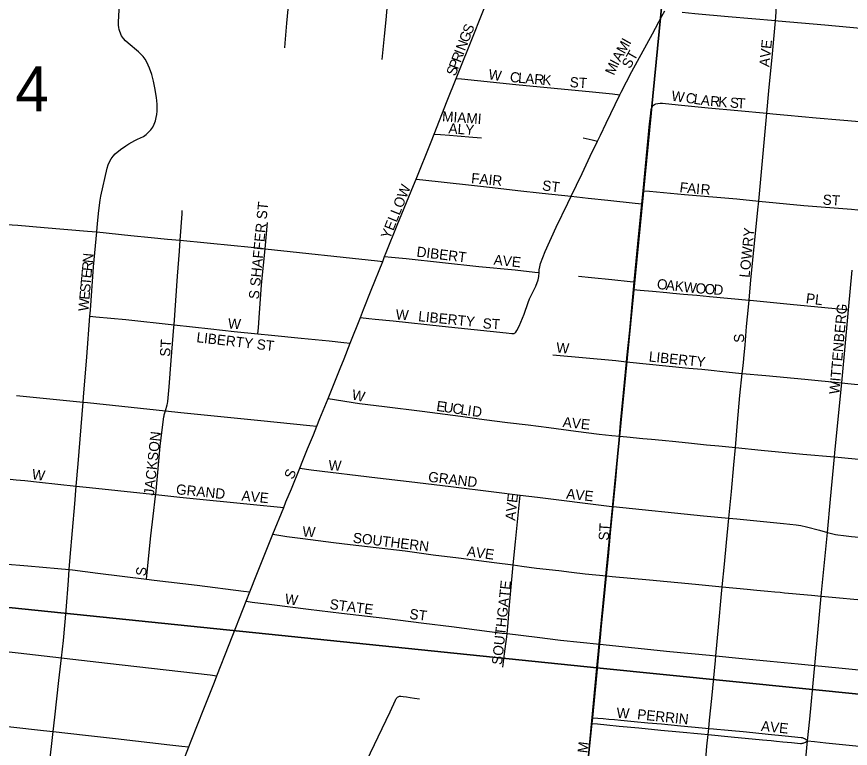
# Model space of a CAD drawing. Extents: x -209 to 4852, y 0 to 905.
# Drawn here: x 96.2 to 111.69, y 254.19 to 267.79 of the extents above; entities that cross this region are included whole.
import ezdxf

# ---------------------------------------------------------------- set-up
doc = ezdxf.new("R2010")
doc.units = 0
for name, color, linetype in [('GM_X_Airport_Location_Class_2', 7, 'Continuous'), ('GM_X_Airport_Location_Class_3', 7, 'Continuous'), ('GM_X_Minor_River', 7, 'Continuous'), ('GM_X_Township_Road_Text', 7, 'Continuous')]:
    doc.layers.add(name, color=color, linetype=linetype)

msp = doc.modelspace()

# ---------------------------------------------------------------- linework, layer by layer
at = {"layer": 'GM_X_Airport_Location_Class_2'}
for points in [[(98.148, 267.436), (98.115, 267.514), (98.106, 267.55), (98.1, 267.588), (98.095, 267.632), (98.095, 267.687), (98.11, 268.03), (98.113, 268.107), (98.116, 268.192), (98.12, 268.319), (98.123, 268.4), (98.126, 268.483), (98.137, 268.607), (98.165, 268.915)], [(101.183, 267.213), (101.192, 267.298), (101.222, 267.669), (101.31, 268.581)], [(110.301, 267.713), (110.307, 267.791), (110.32, 267.982), (110.359, 268.413), (110.36, 268.419)], [(102.994, 266.997), (103.037, 267.427), (103.063, 267.735), (103.102, 268.168), (103.12, 268.388)], [(104.366, 266.644), (104.706, 267.489), (104.801, 267.725), (104.986, 268.2)], [(107.408, 266.341), (107.43, 266.387), (107.627, 266.771), (108.015, 267.474), (108.188, 267.799), (108.242, 267.9)], [(110.301, 267.713), (109.421, 267.791), (108.799, 267.847), (108.564, 267.87)], [(110.137, 265.996), (110.175, 266.413), (110.241, 267.099), (110.301, 267.713)], [(112.145, 267.546), (111.215, 267.631), (110.349, 267.709), (110.301, 267.713)], [(97.767, 264.452), (97.883, 264.977), (97.902, 265.037), (97.924, 265.095), (97.954, 265.149), (97.991, 265.199), (98.034, 265.244), (98.13, 265.324), (98.229, 265.392), (98.282, 265.425), (98.34, 265.46), (98.394, 265.488), (98.449, 265.513), (98.504, 265.538), (98.559, 265.566), (98.605, 265.601), (98.652, 265.642), (98.694, 265.689), (98.729, 265.74), (98.758, 265.795), (98.779, 265.853), (98.795, 265.914), (98.805, 265.975), (98.809, 266.037), (98.809, 266.162), (98.798, 266.286), (98.77, 266.471), (98.744, 266.593), (98.711, 266.714), (98.669, 266.831), (98.618, 266.946), (98.587, 267), (98.552, 267.05), (98.511, 267.097), (98.465, 267.14), (98.27, 267.296), (98.224, 267.339), (98.183, 267.385), (98.148, 267.436)], [(103.955, 265.606), (104.197, 266.225), (104.366, 266.644)], [(104.366, 266.644), (104.468, 266.634), (105.477, 266.531), (106.9, 266.397), (107.272, 266.356), (107.408, 266.341)], [(106.995, 265.478), (107.049, 265.59), (107.156, 265.812), (107.408, 266.341)], [(107.839, 264.555), (107.961, 265.802), (107.982, 265.999), (107.989, 266.069), (107.993, 266.086), (107.999, 266.102), (108.007, 266.117), (108.019, 266.131)], [(108.019, 266.131), (108.034, 266.144), (108.053, 266.157), (108.079, 266.169), (108.113, 266.179), (108.159, 266.182), (108.201, 266.181), (108.491, 266.15), (109.05, 266.099), (109.601, 266.045), (110.137, 265.996)], [(109.988, 264.363), (110.062, 265.18), (110.137, 265.996)], [(110.137, 265.996), (110.252, 265.986), (110.521, 265.961), (111.054, 265.913), (111.497, 265.873), (111.86, 265.84), (111.98, 265.83)], [(103.621, 264.77), (103.899, 265.462), (103.955, 265.606)], [(103.955, 265.606), (104.075, 265.599), (104.243, 265.589), (104.383, 265.576), (104.674, 265.549), (104.835, 265.538)], [(106.504, 264.454), (106.605, 264.656), (106.707, 264.876), (106.859, 265.2), (106.995, 265.478)], [(106.724, 265.538), (106.781, 265.528), (106.893, 265.502), (106.995, 265.478)], [(103.038, 263.332), (103.068, 263.406), (103.273, 263.918), (103.574, 264.652), (103.621, 264.77)], [(103.621, 264.77), (103.748, 264.756), (104.596, 264.663), (105.041, 264.614), (105.51, 264.562), (105.966, 264.513), (106.504, 264.454)], [(107.815, 264.311), (107.828, 264.439), (107.839, 264.555)], [(107.839, 264.555), (107.956, 264.545), (108.608, 264.488), (109.582, 264.402), (109.988, 264.363)], [(97.689, 263.789), (97.704, 263.946), (97.728, 264.191), (97.755, 264.378), (97.767, 264.452)], [(105.907, 263.033), (105.91, 263.083), (105.918, 263.143), (105.934, 263.201), (105.975, 263.315), (106.021, 263.428), (106.226, 263.879), (106.44, 264.324), (106.504, 264.454)], [(106.504, 264.454), (106.821, 264.419), (107.185, 264.38), (107.689, 264.325), (107.815, 264.311)], [(107.674, 262.863), (107.759, 263.76), (107.815, 264.311)], [(109.809, 262.521), (109.844, 262.9), (109.918, 263.637), (109.973, 264.199), (109.988, 264.363)], [(109.988, 264.363), (110.826, 264.284), (111.709, 264.21), (111.826, 264.2)], [(99.241, 263.634), (99.273, 264.125), (99.276, 264.189)], [(96.014, 263.93), (96.224, 263.913), (96.711, 263.873), (97.517, 263.806), (97.689, 263.789)], [(100.817, 263.478), (100.864, 263.968)], [(97.561, 262.221), (97.57, 262.333), (97.631, 263.14), (97.689, 263.789)], [(97.689, 263.789), (98.322, 263.726), (98.699, 263.688), (99.003, 263.658), (99.241, 263.634)], [(99.125, 262.062), (99.158, 262.516), (99.192, 262.967), (99.228, 263.434), (99.241, 263.634)], [(99.241, 263.634), (100.241, 263.535), (100.747, 263.485), (100.817, 263.478)], [(100.683, 261.897), (100.692, 262.01), (100.707, 262.193), (100.751, 262.806), (100.817, 263.478)], [(100.817, 263.478), (102.902, 263.254), (103.003, 263.243)], [(103.003, 263.243), (103.038, 263.332)], [(103.038, 263.332), (103.167, 263.32), (103.437, 263.296), (104.787, 263.15), (105.463, 263.085), (105.831, 263.042), (105.907, 263.033)], [(102.586, 262.2), (102.645, 262.35), (102.789, 262.71), (103.003, 263.243)], [(105.464, 261.913), (105.478, 261.929), (105.495, 261.959), (105.536, 262.037), (105.632, 262.261), (105.705, 262.479), (105.73, 262.543), (105.762, 262.61), (105.848, 262.779), (105.891, 262.897), (105.903, 262.959), (105.907, 263.033)], [(111.655, 262.343), (111.724, 263.079)], [(106.642, 262.968), (106.883, 262.943), (107.256, 262.906), (107.601, 262.871), (107.674, 262.863)], [(107.662, 262.722), (107.674, 262.863)], [(107.531, 261.377), (107.537, 261.447), (107.59, 261.966), (107.648, 262.583), (107.662, 262.722)], [(107.662, 262.722), (107.785, 262.71), (108.013, 262.689), (108.283, 262.664), (108.389, 262.654), (108.593, 262.635), (108.837, 262.612), (109.075, 262.589), (109.809, 262.521)], [(109.683, 261.16), (109.692, 261.248), (109.702, 261.36), (109.716, 261.504), (109.733, 261.685), (109.763, 262.03), (109.797, 262.39), (109.809, 262.521)], [(109.809, 262.521), (109.826, 262.519), (110.569, 262.444), (111.54, 262.354), (111.655, 262.343)], [(97.438, 260.627), (97.445, 260.72), (97.502, 261.465), (97.561, 262.221)], [(97.561, 262.221), (97.672, 262.211), (98.227, 262.159), (99.125, 262.062)], [(111.529, 260.984), (111.599, 261.731), (111.655, 262.343)], [(98.965, 260.465), (98.997, 260.574), (99.003, 260.603), (99.008, 260.638), (99.035, 260.908), (99.073, 261.402), (99.097, 261.712), (99.123, 262.021), (99.125, 262.062)], [(99.125, 262.062), (99.807, 261.989), (100.245, 261.941), (100.683, 261.897)], [(102.4, 261.725), (102.586, 262.2)], [(102.586, 262.2), (102.742, 262.183), (102.86, 262.171), (103.197, 262.135), (104.105, 262.038), (105.295, 261.911), (105.403, 261.901), (105.422, 261.901), (105.438, 261.901), (105.447, 261.903), (105.453, 261.905), (105.464, 261.913)], [(100.683, 261.897), (100.937, 261.872), (101.485, 261.817), (102.008, 261.764), (102.281, 261.737), (102.4, 261.725)], [(101.991, 260.691), (102.214, 261.249), (102.285, 261.432), (102.4, 261.725)], [(106.165, 261.503), (107.332, 261.397), (107.531, 261.377)], [(107.4, 259.993), (107.42, 260.233), (107.475, 260.8), (107.531, 261.377)], [(107.531, 261.377), (108.686, 261.26), (108.933, 261.236), (109.102, 261.219), (109.32, 261.197), (109.621, 261.166), (109.683, 261.16)], [(109.553, 259.782), (109.56, 259.859), (109.594, 260.249), (109.637, 260.747), (109.683, 261.16)], [(109.683, 261.16), (110.118, 261.119), (110.842, 261.05), (111.529, 260.984)], [(111.394, 259.608), (111.401, 259.686), (111.478, 260.431), (111.529, 260.984)], [(111.529, 260.984), (111.645, 260.973), (112.588, 260.881)], [(96.2, 260.751), (97.438, 260.627)], [(101.778, 260.176), (101.835, 260.32), (101.991, 260.691)], [(101.991, 260.691), (102.568, 260.602), (103.032, 260.544), (103.732, 260.457), (104.447, 260.363), (104.791, 260.318), (105.081, 260.28), (105.322, 260.25), (105.703, 260.201), (106.091, 260.152), (106.59, 260.087), (107.024, 260.032), (107.258, 260.005), (107.4, 259.993)], [(97.309, 259.064), (97.345, 259.479), (97.438, 260.627)], [(97.438, 260.627), (97.52, 260.618), (98.965, 260.465)], [(98.784, 258.909), (98.819, 259.249), (98.865, 259.808), (98.904, 260.11), (98.936, 260.353), (98.94, 260.371), (98.944, 260.391), (98.965, 260.465)], [(98.965, 260.465), (99.25, 260.435), (100.24, 260.337), (100.74, 260.284), (101.648, 260.19), (101.778, 260.176)], [(101.459, 259.396), (101.519, 259.538), (101.607, 259.76), (101.715, 260.019), (101.778, 260.176)], [(107.285, 258.685), (107.333, 259.179), (107.364, 259.551), (107.4, 259.993)], [(107.4, 259.993), (107.54, 259.98), (107.835, 259.951), (107.995, 259.935), (108.191, 259.916), (108.447, 259.891), (108.737, 259.862), (109.017, 259.834), (109.248, 259.812), (109.432, 259.793), (109.553, 259.782)], [(109.433, 258.468), (109.479, 258.964), (109.525, 259.458), (109.553, 259.782)], [(109.553, 259.782), (110.031, 259.734), (110.805, 259.658), (111.394, 259.608)], [(111.263, 258.205), (111.321, 258.823), (111.394, 259.608)], [(111.394, 259.608), (111.527, 259.597), (111.844, 259.567), (112.075, 259.545), (112.373, 259.516), (112.687, 259.486), (113.077, 259.449), (113.461, 259.413), (113.579, 259.404)], [(101.162, 258.667), (101.204, 258.771), (101.305, 259.012), (101.459, 259.396)], [(101.459, 259.396), (101.674, 259.369), (102.905, 259.219), (103.493, 259.149), (104.265, 259.057), (105.068, 258.959), (105.554, 258.899)], [(96.081, 259.194), (96.19, 259.183), (96.35, 259.166), (96.624, 259.137), (97.309, 259.064)], [(97.177, 257.512), (97.192, 257.743), (97.28, 258.735), (97.309, 259.064)], [(97.309, 259.064), (97.555, 259.038), (98.61, 258.928), (98.784, 258.909)], [(98.613, 257.336), (98.626, 257.457), (98.658, 257.774), (98.695, 258.138), (98.74, 258.508), (98.781, 258.879), (98.784, 258.909)], [(98.784, 258.909), (99.231, 258.862), (100.661, 258.718), (101.039, 258.679), (101.162, 258.667)], [(105.426, 257.599), (105.467, 258.029), (105.542, 258.773), (105.554, 258.899)], [(105.554, 258.899), (105.875, 258.86), (107.212, 258.693), (107.285, 258.685)], [(100.963, 258.174), (101.162, 258.667)], [(107.16, 257.396), (107.194, 257.755), (107.236, 258.188), (107.285, 258.685)], [(107.285, 258.685), (108.959, 258.513), (109.433, 258.468)], [(109.31, 257.191), (109.35, 257.614), (109.391, 258.019), (109.433, 258.468)], [(109.433, 258.468), (109.58, 258.454), (110.445, 258.372), (110.682, 258.345), (110.772, 258.331), (110.874, 258.309), (111.114, 258.244), (111.263, 258.205)], [(111.149, 257.022), (111.155, 257.089), (111.204, 257.584), (111.263, 258.205)], [(111.263, 258.205), (111.363, 258.179), (111.415, 258.167), (111.455, 258.16), (111.563, 258.146), (111.711, 258.128), (112.043, 258.1), (112.577, 258.05), (113.02, 258.014), (113.445, 257.972)], [(100.534, 257.098), (100.664, 257.426), (100.963, 258.174)], [(100.963, 258.174), (101.222, 258.131), (101.52, 258.091), (102.087, 258.019), (102.399, 257.98), (103.416, 257.859), (103.939, 257.787), (104.411, 257.729), (105.071, 257.647), (105.426, 257.599)], [(95.954, 257.623), (96.41, 257.58), (96.967, 257.534), (97.177, 257.512)], [(105.312, 256.323), (105.325, 256.446), (105.355, 256.852), (105.426, 257.599)], [(105.426, 257.599), (105.586, 257.578), (105.862, 257.54), (106.273, 257.493), (106.507, 257.465), (106.765, 257.434), (107.16, 257.396)], [(97.034, 255.871), (97.069, 256.193), (97.123, 256.75), (97.164, 257.308), (97.177, 257.512)], [(97.177, 257.512), (97.236, 257.506), (97.707, 257.449), (98.613, 257.336)], [(98.613, 257.336), (98.754, 257.319), (99.555, 257.222), (100.417, 257.113), (100.534, 257.098)], [(107.036, 256.127), (107.055, 256.316), (107.069, 256.465), (107.112, 256.889), (107.16, 257.396)], [(107.16, 257.396), (107.265, 257.386), (107.956, 257.32), (108.812, 257.239), (109.31, 257.191)], [(109.191, 255.911), (109.24, 256.443), (109.298, 257.06), (109.31, 257.191)], [(109.31, 257.191), (109.772, 257.147), (109.955, 257.13), (110.157, 257.112), (110.289, 257.1), (110.387, 257.091), (110.467, 257.084), (110.615, 257.07), (110.754, 257.058), (110.971, 257.038), (111.149, 257.022)], [(100.465, 256.925), (100.534, 257.098)], [(111.03, 255.729), (111.095, 256.407), (111.149, 257.022)], [(111.149, 257.022), (111.486, 256.991), (111.756, 256.966), (112.193, 256.926), (112.709, 256.879), (113.176, 256.834), (113.339, 256.818)], [(99.922, 255.54), (100.15, 256.118), (100.465, 256.925)], [(100.465, 256.925), (100.578, 256.91), (100.942, 256.864), (101.626, 256.78), (102.239, 256.705), (103.041, 256.607), (103.766, 256.518), (104.278, 256.455), (105.224, 256.333), (105.312, 256.323)], [(105.236, 255.697), (105.266, 255.944), (105.289, 256.133), (105.305, 256.261), (105.312, 256.323)], [(105.312, 256.323), (105.87, 256.255), (106.307, 256.202), (107.036, 256.127)], [(94.6, 256.146), (94.691, 256.136), (95.182, 256.083), (96.226, 255.963), (97.034, 255.871)], [(106.906, 254.759), (106.968, 255.403), (107.023, 256.003), (107.036, 256.127)], [(107.036, 256.127), (108.339, 255.992), (109.072, 255.922), (109.191, 255.911)], [(96.879, 254.502), (96.908, 254.77), (96.987, 255.45), (97.034, 255.871)], [(97.034, 255.871), (97.086, 255.865), (97.886, 255.772), (99.795, 255.554), (99.922, 255.54)], [(109.058, 254.562), (109.073, 254.715), (109.117, 255.119), (109.183, 255.822), (109.191, 255.911)], [(109.191, 255.911), (109.619, 255.869), (110.201, 255.812), (110.719, 255.761), (111.03, 255.729)], [(110.895, 254.329), (110.936, 254.735), (111.018, 255.602), (111.03, 255.729)], [(111.03, 255.729), (111.478, 255.685), (112.034, 255.629), (113.214, 255.516)], [(99.4, 254.216), (99.444, 254.329), (99.679, 254.924), (99.874, 255.419), (99.922, 255.54)], [(103.24, 255.085), (103.248, 255.102), (103.256, 255.116), (103.266, 255.13), (103.274, 255.14), (103.286, 255.148), (103.299, 255.154), (103.313, 255.157), (103.327, 255.159), (103.34, 255.159), (103.38, 255.154), (103.441, 255.145), (103.512, 255.135), (103.594, 255.124), (103.683, 255.111)], [(102.594, 253.729), (102.626, 253.796), (103.138, 254.867), (103.24, 255.085)], [(94.441, 254.773), (94.823, 254.731), (95.384, 254.669), (96.095, 254.59), (96.702, 254.523), (96.879, 254.502)], [(106.751, 253.268), (106.761, 253.374), (106.787, 253.622), (106.815, 253.892), (106.833, 254.056), (106.89, 254.598), (106.895, 254.653)], [(106.895, 254.653), (106.906, 254.759)], [(106.895, 254.653), (106.991, 254.643), (107.167, 254.626), (107.396, 254.603), (107.76, 254.569), (108.17, 254.53), (108.515, 254.498), (108.916, 254.46), (109.047, 254.448)], [(106.906, 254.759), (106.998, 254.751), (107.097, 254.743), (107.201, 254.734), (107.305, 254.725), (107.423, 254.715), (107.674, 254.691), (107.927, 254.667), (108.181, 254.643), (108.542, 254.608), (108.936, 254.571), (109.058, 254.562)], [(96.728, 253.147), (96.744, 253.286), (96.808, 253.842), (96.879, 254.502)], [(96.879, 254.502), (97.483, 254.434), (98.035, 254.371), (99.044, 254.256), (99.269, 254.23), (99.4, 254.216)], [(109.047, 254.448), (109.058, 254.562)], [(109.058, 254.562), (109.146, 254.555), (109.211, 254.549), (109.351, 254.535), (109.489, 254.522), (109.696, 254.501), (109.877, 254.483), (110.161, 254.455), (110.476, 254.424), (110.778, 254.394), (110.793, 254.391), (110.808, 254.386), (110.821, 254.381), (110.835, 254.375), (110.851, 254.365), (110.866, 254.355), (110.895, 254.329)], [(108.92, 253.057), (108.933, 253.184), (108.959, 253.482), (109.004, 253.992), (109.026, 254.23), (109.047, 254.448)], [(109.047, 254.448), (109.477, 254.406), (110.057, 254.349), (110.22, 254.333), (110.318, 254.324), (110.438, 254.312), (110.517, 254.304), (110.598, 254.296), (110.765, 254.28), (110.782, 254.282), (110.796, 254.284), (110.813, 254.287), (110.826, 254.291), (110.845, 254.298), (110.859, 254.306), (110.895, 254.329)], [(110.754, 252.877), (110.842, 253.806), (110.895, 254.329)], [(110.895, 254.329), (111.024, 254.316), (111.236, 254.295), (112.038, 254.215), (112.54, 254.165)], [(98.884, 252.892), (99.082, 253.4), (99.4, 254.216)]]:
    msp.add_lwpolyline(points, dxfattribs=at)
at = {"layer": 'GM_X_Minor_River'}
for points in [[(88.927, 277.384), (108.909, 275.428), (106.979, 255.688), (87.119, 257.725)], [(108.909, 275.428), (129.104, 273.545), (127.195, 253.652), (106.979, 255.688)], [(87.119, 257.725), (106.979, 255.688), (105.036, 235.054), (84.904, 237.096)], [(106.979, 255.688), (127.195, 253.652), (125.307, 233.161), (105.036, 235.054)]]:
    msp.add_lwpolyline(points, close=True, dxfattribs=at)

# ---------------------------------------------------------------- texts
at = {"layer": 'GM_X_Airport_Location_Class_3'}
for s, height, rotation, p in [('S', 0.189, 66.5646, (104.648, 267.452)), ('G', 0.189, 69.1037, (104.59, 267.298)), ('N', 0.189, 69.122, (104.53, 267.143)), ('M', 0.189, 60.6279, (107.496, 267.086)), ('I', 0.189, 60.6525, (107.594, 267.261)), ('AVE', 0.1894, 84.0895, (110.183, 266.85)), ('I', 0.189, 69.0833, (104.5, 267.065)), ('ST', 0.1894, 60.2568, (107.594, 266.81)), ('R', 0.189, 69.1026, (104.447, 266.925)), ('A', 0.189, 60.6428, (107.414, 266.941)), ('S', 0.189, 69.1066, (104.352, 266.675)), ('P', 0.189, 69.0978, (104.399, 266.8)), ('M', 0.189, 66.5479, (107.298, 266.689)), ('I', 0.189, 61.7732, (107.375, 266.869)), ('W', 0.189, 351.2507, (104.957, 266.631)), ('C', 0.189, 353.4895, (105.357, 266.581)), ('L', 0.189, 355.0177, (105.511, 266.564)), ('A', 0.189, 355.3082, (105.645, 266.552)), ('R', 0.189, 355.3359, (105.811, 266.539)), ('K', 0.189, 355.3289, (105.961, 266.526)), ('ST', 0.1894, 356.4254, (106.471, 266.482)), ('W', 0.189, 351.9032, (108.357, 266.231)), ('C', 0.189, 351.8968, (108.621, 266.194)), ('L', 0.189, 351.9048, (108.77, 266.173)), ('A', 0.189, 352.6608, (108.904, 266.154)), ('R', 0.189, 355.2993, (109.079, 266.131)), ('K', 0.189, 355.8094, (109.23, 266.119)), ('S', 0.189, 355.8171, (109.446, 266.103)), ('T', 0.189, 355.8035, (109.579, 266.093)), ('MIAMI', 0.1894, 356.0936, (104.101, 265.846)), ('ALY', 0.1894, 356.0531, (104.219, 265.623)), ('FAIR', 0.1894, 354.644, (104.639, 264.698)), ('ST', 0.1894, 352.8716, (105.956, 264.565)), ('F', 0.189, 352.492, (108.509, 264.531)), ('A', 0.189, 355.4206, (108.652, 264.513)), ('YELLOW', 0.1894, 68.1958, (103.135, 263.643)), ('I', 0.189, 355.7629, (108.819, 264.499)), ('R', 0.189, 355.7659, (108.903, 264.493)), ('ST', 0.1894, 356.4254, (111.171, 264.298)), ('S SHAFFER ST', 0.18939, 84.4098, (100.7, 262.532)), ('LOWRY', 0.1894, 84.3995, (109.816, 262.933)), ('DIBERT', 0.1894, 353.1571, (103.623, 263.332)), ('N', 0.189, 84.7331, (97.614, 263.205)), ('AVE', 0.1894, 354.0932, (105.056, 263.182)), ('R', 0.189, 84.7231, (97.6, 263.055)), ('E', 0.189, 84.719, (97.587, 262.923)), ('T', 0.189, 84.7502, (97.575, 262.79)), ('O', 0.189, 353.6695, (108.089, 262.732)), ('A', 0.189, 353.6779, (108.255, 262.713)), ('K', 0.189, 353.6695, (108.42, 262.695)), ('W', 0.189, 353.7934, (108.586, 262.676)), ('O', 0.189, 355.3756, (108.808, 262.653)), ('E', 0.189, 84.7202, (97.551, 262.524)), ('S', 0.189, 84.7202, (97.563, 262.657)), ('O', 0.189, 356.0236, (108.976, 262.639)), ('D', 0.189, 356.0461, (109.142, 262.627)), ('W', 0.189, 85.2196, (97.533, 262.309)), ('PL', 0.1894, 352.8716, (110.856, 262.465)), ('WITTENBERG', 0.1894, 84.9208, (111.483, 260.766)), ('W', 0.189, 355.6039, (103.238, 262.165)), ('LIBERTY', 0.1894, 354.1926, (103.655, 262.132)), ('W', 0.189, 355.5955, (100.121, 261.998)), ('ST', 0.1894, 356.4186, (104.854, 261.998)), ('LIBERTY ST', 0.1894, 353.4211, (99.534, 261.741)), ('ST', 0.1894, 86.4258, (99.05, 261.465)), ('S', 0.189, 90, (109.716, 261.73)), ('W', 0.189, 355.6039, (106.221, 261.548)), ('LIBERTY', 0.1894, 354.1926, (107.939, 261.382)), ('W', 0.189, 347.9663, (102.416, 260.679)), ('E', 0.189, 351.7192, (103.99, 260.465)), ('U', 0.189, 351.7383, (104.122, 260.446)), ('C', 0.189, 351.7274, (104.287, 260.422)), ('L', 0.189, 351.7192, (104.436, 260.4)), ('I', 0.189, 351.7426, (104.568, 260.381)), ('D', 0.189, 352.728, (104.654, 260.368)), ('AVE', 0.1894, 354.0932, (106.339, 260.165)), ('JACKSON', 0.1894, 83.7461, (98.75, 258.882)), ('W', 0.189, 355.6039, (101.988, 259.365)), ('W', 0.189, 351.2564, (96.474, 259.198)), ('S', 0.189, 66.8127, (101.336, 259.177)), ('GRAND', 0.1894, 353.2341, (103.839, 259.148)), ('GRAND', 0.1894, 354.1746, (99.155, 258.915)), ('AVE', 0.1894, 354.0932, (100.372, 258.798)), ('AVE', 0.1894, 354.094, (106.405, 258.832)), ('E', 0.189, 82.9614, (105.497, 258.746)), ('V', 0.189, 84.6597, (105.482, 258.582)), ('A', 0.189, 84.6374, (105.466, 258.416)), ('ST', 0.1894, 86.4258, (107.2, 258.048)), ('W', 0.189, 355.5955, (101.505, 258.132)), ('SOUTHERN', 0.1894, 353.2102, (102.439, 258.015)), ('AVE', 0.1894, 352.1481, (104.557, 257.765)), ('S', 0.189, 82.88, (98.6, 257.384)), ('SOUTHGATE', 0.1894, 83.8105, (105.216, 255.734)), ('W', 0.189, 351.2589, (101.174, 256.881)), ('STATE', 0.1894, 352.4764, (102.007, 256.782)), ('ST', 0.1894, 352.8783, (103.49, 256.598)), ('W', 0.189, 357.0007, (107.343, 254.757)), ('PERRIN', 0.1894, 354.174, (107.723, 254.732)), ('AVE', 0.1894, 354.0928, (110.023, 254.515)), ('M', 0.189, 83.172, (106.806, 254.094))]:
    msp.add_text(s, height=height, rotation=rotation, dxfattribs=at).set_placement(p)
at = {"layer": 'GM_X_Township_Road_Text'}
msp.add_text('4', height=0.837, rotation=0, dxfattribs=at).set_placement((96.177, 266.029))

doc.saveas('drawing.dxf')
